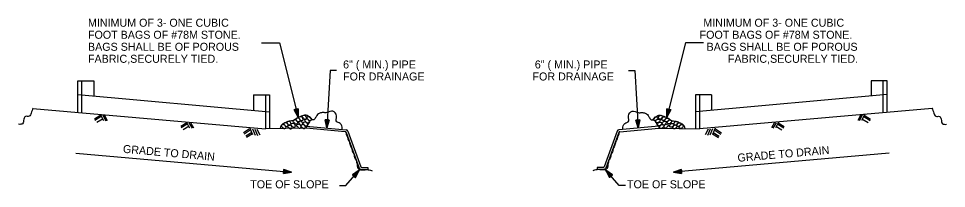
# Model space of a CAD drawing. Extents: x -41 to 251, y -169 to 237.
# Drawn here: x -40.56 to -7.34, y -129.36 to -123.29 of the extents above; entities that cross this region are included whole.
import ezdxf

# ---------------------------------------------------------------- set-up
doc = ezdxf.new("R2010")
doc.units = 0
for name, color, linetype in [('Arrowhead Terminators CELL', 7, 'Continuous'), ('Default', 7, 'Continuous'), ('Dimension Lines CELL', 7, 'Continuous'), ('Mis Object Lines', 7, 'Continuous'), ('Text CELL', 7, 'Continuous')]:
    doc.layers.add(name, color=color, linetype=linetype)

msp = doc.modelspace()

# ---------------------------------------------------------------- linework, layer by layer
at = {"layer": 'Arrowhead Terminators CELL'}
for points in [[(-30.624, -126.528), (-30.638, -126.531), (-30.554, -126.806), (-30.651, -126.535), (-30.665, -126.538), (-30.554, -126.806), (-30.679, -126.542), (-30.693, -126.545), (-30.554, -126.806), (-30.554, -126.51), (-30.568, -126.514), (-30.554, -126.806), (-30.582, -126.517), (-30.596, -126.521), (-30.554, -126.806), (-30.61, -126.524), (-30.693, -126.545), (-30.554, -126.51), (-30.554, -126.806), (-30.693, -126.545)], [(-17.277, -126.528), (-17.263, -126.531), (-17.347, -126.806), (-17.249, -126.535), (-17.236, -126.538), (-17.347, -126.806), (-17.222, -126.542), (-17.208, -126.545), (-17.347, -126.806), (-17.347, -126.51), (-17.333, -126.514), (-17.347, -126.806), (-17.319, -126.517), (-17.305, -126.521), (-17.347, -126.806), (-17.291, -126.524), (-17.208, -126.545), (-17.347, -126.51), (-17.347, -126.806), (-17.208, -126.545)], [(-29.507, -126.909), (-29.521, -126.908), (-29.524, -127.195), (-29.535, -126.907), (-29.549, -126.906), (-29.524, -127.195), (-29.564, -126.905), (-29.578, -126.905), (-29.524, -127.195), (-29.435, -126.913), (-29.449, -126.912), (-29.524, -127.195), (-29.464, -126.911), (-29.478, -126.911), (-29.524, -127.195), (-29.492, -126.91), (-29.578, -126.905), (-29.435, -126.913), (-29.524, -127.195), (-29.578, -126.905)], [(-18.394, -126.909), (-18.38, -126.908), (-18.377, -127.195), (-18.366, -126.907), (-18.352, -126.906), (-18.377, -127.195), (-18.337, -126.905), (-18.323, -126.905), (-18.377, -127.195), (-18.466, -126.913), (-18.452, -126.912), (-18.377, -127.195), (-18.437, -126.911), (-18.423, -126.911), (-18.377, -127.195), (-18.409, -126.91), (-18.323, -126.905), (-18.466, -126.913), (-18.377, -127.195), (-18.323, -126.905)], [(-31.073, -128.751), (-31.074, -128.765), (-30.787, -128.776), (-31.075, -128.78), (-31.076, -128.794), (-30.787, -128.776), (-31.077, -128.808), (-31.079, -128.823), (-30.787, -128.776), (-31.066, -128.68), (-31.068, -128.694), (-30.787, -128.776), (-31.069, -128.708), (-31.07, -128.723), (-30.787, -128.776), (-31.071, -128.737), (-31.079, -128.823), (-31.066, -128.68), (-30.787, -128.776), (-31.079, -128.823)], [(-28.553, -128.922), (-28.543, -128.932), (-28.364, -128.708), (-28.532, -128.941), (-28.521, -128.951), (-28.364, -128.708), (-28.511, -128.96), (-28.5, -128.97), (-28.364, -128.708), (-28.607, -128.875), (-28.596, -128.884), (-28.364, -128.708), (-28.586, -128.894), (-28.575, -128.903), (-28.364, -128.708), (-28.564, -128.913), (-28.5, -128.97), (-28.607, -128.875), (-28.364, -128.708), (-28.5, -128.97)], [(-19.348, -128.922), (-19.358, -128.932), (-19.537, -128.708), (-19.369, -128.941), (-19.38, -128.951), (-19.537, -128.708), (-19.39, -128.96), (-19.401, -128.97), (-19.537, -128.708), (-19.294, -128.875), (-19.305, -128.884), (-19.537, -128.708), (-19.315, -128.894), (-19.326, -128.903), (-19.537, -128.708), (-19.337, -128.913), (-19.401, -128.97), (-19.294, -128.875), (-19.537, -128.708), (-19.401, -128.97)], [(-16.828, -128.751), (-16.827, -128.765), (-17.114, -128.776), (-16.826, -128.78), (-16.825, -128.794), (-17.114, -128.776), (-16.824, -128.808), (-16.822, -128.823), (-17.114, -128.776), (-16.835, -128.68), (-16.833, -128.694), (-17.114, -128.776), (-16.832, -128.708), (-16.831, -128.723), (-17.114, -128.776), (-16.83, -128.737), (-16.822, -128.823), (-16.835, -128.68), (-17.114, -128.776), (-16.822, -128.823)]]:
    msp.add_lwpolyline(points, dxfattribs=at)
at = {"layer": 'Default'}
for p, q in [((-38.286, -126.661), (-38.286, -125.508)), ((-38.286, -125.508), (-37.857, -125.508)), ((-9.615, -125.508), (-10.044, -125.508)), ((-9.615, -126.661), (-9.615, -125.508)), ((-32.147, -126.014), (-31.717, -126.014)), ((-31.717, -126.014), (-31.717, -127.227)), ((-31.717, -126.014), (-31.574, -126.014)), ((-31.574, -126.014), (-31.574, -127.227)), ((-16.184, -126.014), (-16.327, -126.014)), ((-16.327, -126.014), (-16.327, -127.227)), ((-15.754, -126.014), (-16.184, -126.014)), ((-16.184, -126.014), (-16.184, -127.227)), ((-30.261, -127.137), (-30.267, -127.209)), ((-30.261, -127.137), (-28.834, -127.262)), ((-17.64, -127.137), (-19.067, -127.262)), ((-17.64, -127.137), (-17.634, -127.209)), ((-30.267, -127.209), (-31.723, -127.223)), ((-28.863, -127.332), (-30.267, -127.209)), ((-28.833, -127.355), (-28.368, -128.632)), ((-28.773, -127.309), (-28.309, -128.584)), ((-19.128, -127.309), (-19.592, -128.584)), ((-19.068, -127.355), (-19.533, -128.632)), ((-19.038, -127.332), (-17.634, -127.209)), ((-17.634, -127.209), (-16.178, -127.223)), ((-28.301, -128.679), (-28.055, -128.679)), ((-28.276, -128.608), (-28.055, -128.608)), ((-28.055, -128.608), (-28.055, -128.679)), ((-19.625, -128.608), (-19.846, -128.608)), ((-19.846, -128.608), (-19.846, -128.679)), ((-19.6, -128.679), (-19.846, -128.679))]:
    msp.add_line(p, q, dxfattribs=at)
for points in [[(-38.429, -126.645), (-38.429, -125.508), (-38.286, -125.508), (-38.286, -125.512)], [(-9.472, -126.645), (-9.472, -125.508), (-9.615, -125.508), (-9.615, -125.512)], [(-40.051, -126.495), (-31.723, -127.223)], [(-7.85, -126.495), (-16.178, -127.223)]]:
    msp.add_lwpolyline(points, dxfattribs=at)
for centre, radius, start, end in [((-28.866, -127.367), 0.0358, 20, 85), ((-28.841, -127.334), 0.0716, 20.0004, 85.0001), ((-19.06, -127.334), 0.0716, 94.9999, 159.9996), ((-19.035, -127.367), 0.0358, 95, 160), ((-28.301, -128.608), 0.0716, 200.0001, 270), ((-28.276, -128.572), 0.0358, 200.0006, 270), ((-19.625, -128.572), 0.0358, 270, 339.9994), ((-19.6, -128.608), 0.0716, 270, 339.9999)]:
    msp.add_arc(centre, radius, start, end, dxfattribs=at)
for points in [[(-40.037, -126.487), (-40.107, -126.666), (-40.177, -126.776), (-40.307, -126.786), (-40.367, -126.876), (-40.417, -127.046), (-40.557, -127.066)], [(-7.864, -126.487), (-7.794, -126.666), (-7.724, -126.776), (-7.594, -126.786), (-7.534, -126.876), (-7.484, -127.046), (-7.344, -127.066)], [(-30.05, -126.897), (-30.159, -126.794), (-30.305, -126.739), (-30.487, -126.8), (-30.597, -126.848), (-30.712, -126.927), (-30.87, -126.958), (-31.022, -127.012), (-31.156, -127.11), (-31.192, -127.207)], [(-30.469, -126.939), (-30.53, -126.848), (-30.585, -126.848), (-30.639, -126.885), (-30.621, -126.909), (-30.585, -126.952), (-30.542, -126.982), (-30.481, -126.964), (-30.469, -126.945)], [(-30.366, -126.891), (-30.427, -126.8), (-30.481, -126.8), (-30.536, -126.836), (-30.518, -126.86), (-30.481, -126.903), (-30.439, -126.933), (-30.378, -126.915), (-30.366, -126.897)], [(-30.244, -126.836), (-30.305, -126.745), (-30.36, -126.745), (-30.415, -126.781), (-30.396, -126.806), (-30.36, -126.848), (-30.317, -126.879), (-30.256, -126.86), (-30.244, -126.842)], [(-28.968, -127.231), (-29.047, -127.031), (-29.169, -126.976), (-29.181, -126.769), (-29.302, -126.593), (-29.527, -126.648), (-29.655, -126.648), (-29.776, -126.666), (-29.91, -126.794), (-29.983, -126.903), (-30.086, -126.915), (-30.165, -127.012), (-30.25, -127.134)], [(-30.074, -126.891), (-30.135, -126.8), (-30.19, -126.8), (-30.244, -126.836), (-30.226, -126.86), (-30.19, -126.903), (-30.147, -126.933), (-30.086, -126.915), (-30.074, -126.897)], [(-18.933, -127.231), (-18.854, -127.031), (-18.732, -126.976), (-18.72, -126.769), (-18.599, -126.593), (-18.374, -126.648), (-18.246, -126.648), (-18.125, -126.666), (-17.991, -126.794), (-17.918, -126.903), (-17.815, -126.915), (-17.736, -127.012), (-17.651, -127.134)], [(-17.851, -126.897), (-17.742, -126.794), (-17.596, -126.739), (-17.414, -126.8), (-17.304, -126.848), (-17.189, -126.927), (-17.031, -126.958), (-16.879, -127.012), (-16.745, -127.11), (-16.709, -127.207)], [(-17.827, -126.891), (-17.766, -126.8), (-17.711, -126.8), (-17.657, -126.836), (-17.675, -126.86), (-17.711, -126.903), (-17.754, -126.933), (-17.815, -126.915), (-17.827, -126.897)], [(-17.657, -126.836), (-17.596, -126.745), (-17.541, -126.745), (-17.486, -126.781), (-17.505, -126.806), (-17.541, -126.848), (-17.584, -126.879), (-17.644, -126.86), (-17.657, -126.842)], [(-17.535, -126.891), (-17.474, -126.8), (-17.42, -126.8), (-17.365, -126.836), (-17.383, -126.86), (-17.42, -126.903), (-17.462, -126.933), (-17.523, -126.915), (-17.535, -126.897)], [(-17.432, -126.939), (-17.371, -126.848), (-17.316, -126.848), (-17.262, -126.885), (-17.28, -126.909), (-17.316, -126.952), (-17.359, -126.982), (-17.42, -126.964), (-17.432, -126.945)], [(-30.986, -127.17), (-31.046, -127.079), (-31.101, -127.079), (-31.156, -127.116), (-31.138, -127.14), (-31.101, -127.183), (-31.059, -127.213), (-30.998, -127.195), (-30.986, -127.176)], [(-30.895, -127.104), (-30.955, -127.012), (-31.01, -127.012), (-31.065, -127.049), (-31.046, -127.073), (-31.01, -127.116), (-30.968, -127.146), (-30.907, -127.128), (-30.895, -127.11)], [(-30.797, -127.055), (-30.858, -126.964), (-30.913, -126.964), (-30.968, -127), (-30.949, -127.025), (-30.913, -127.067), (-30.87, -127.097), (-30.81, -127.079), (-30.797, -127.061)], [(-30.761, -127.183), (-30.822, -127.091), (-30.876, -127.091), (-30.931, -127.128), (-30.913, -127.152), (-30.876, -127.195), (-30.834, -127.225), (-30.773, -127.207), (-30.761, -127.189)], [(-30.645, -127.128), (-30.706, -127.037), (-30.761, -127.037), (-30.816, -127.073), (-30.797, -127.097), (-30.761, -127.14), (-30.718, -127.17), (-30.658, -127.152), (-30.645, -127.134)], [(-30.566, -127.006), (-30.627, -126.915), (-30.682, -126.915), (-30.737, -126.952), (-30.718, -126.976), (-30.682, -127.018), (-30.639, -127.049), (-30.579, -127.031), (-30.566, -127.012)], [(-30.439, -127.158), (-30.5, -127.067), (-30.554, -127.067), (-30.609, -127.104), (-30.591, -127.128), (-30.554, -127.17), (-30.512, -127.201), (-30.451, -127.183), (-30.439, -127.164)], [(-30.378, -127.049), (-30.439, -126.958), (-30.493, -126.958), (-30.548, -126.994), (-30.53, -127.018), (-30.493, -127.061), (-30.451, -127.091), (-30.39, -127.073), (-30.378, -127.055)], [(-30.287, -127.17), (-30.348, -127.079), (-30.402, -127.079), (-30.457, -127.116), (-30.439, -127.14), (-30.402, -127.183), (-30.36, -127.213), (-30.299, -127.195), (-30.287, -127.176)], [(-30.208, -127.079), (-30.269, -126.988), (-30.323, -126.988), (-30.378, -127.025), (-30.36, -127.049), (-30.323, -127.091), (-30.281, -127.122), (-30.22, -127.104), (-30.208, -127.085)], [(-30.147, -126.976), (-30.208, -126.885), (-30.263, -126.885), (-30.317, -126.921), (-30.299, -126.945), (-30.263, -126.988), (-30.22, -127.018), (-30.159, -127), (-30.147, -126.982)], [(-17.754, -126.976), (-17.693, -126.885), (-17.638, -126.885), (-17.584, -126.921), (-17.602, -126.945), (-17.638, -126.988), (-17.681, -127.018), (-17.742, -127), (-17.754, -126.982)], [(-17.693, -127.079), (-17.632, -126.988), (-17.578, -126.988), (-17.523, -127.025), (-17.541, -127.049), (-17.578, -127.091), (-17.62, -127.122), (-17.681, -127.104), (-17.693, -127.085)], [(-17.614, -127.17), (-17.553, -127.079), (-17.499, -127.079), (-17.444, -127.116), (-17.462, -127.14), (-17.499, -127.183), (-17.541, -127.213), (-17.602, -127.195), (-17.614, -127.176)], [(-17.523, -127.049), (-17.462, -126.958), (-17.408, -126.958), (-17.353, -126.994), (-17.371, -127.018), (-17.408, -127.061), (-17.45, -127.091), (-17.511, -127.073), (-17.523, -127.055)], [(-17.462, -127.158), (-17.401, -127.067), (-17.347, -127.067), (-17.292, -127.104), (-17.31, -127.128), (-17.347, -127.17), (-17.389, -127.201), (-17.45, -127.183), (-17.462, -127.164)], [(-17.335, -127.006), (-17.274, -126.915), (-17.219, -126.915), (-17.164, -126.952), (-17.183, -126.976), (-17.219, -127.018), (-17.262, -127.049), (-17.322, -127.031), (-17.335, -127.012)], [(-17.256, -127.128), (-17.195, -127.037), (-17.14, -127.037), (-17.085, -127.073), (-17.104, -127.097), (-17.14, -127.14), (-17.183, -127.17), (-17.243, -127.152), (-17.256, -127.134)], [(-17.14, -127.183), (-17.079, -127.091), (-17.025, -127.091), (-16.97, -127.128), (-16.988, -127.152), (-17.025, -127.195), (-17.067, -127.225), (-17.128, -127.207), (-17.14, -127.189)], [(-17.104, -127.055), (-17.043, -126.964), (-16.988, -126.964), (-16.933, -127), (-16.952, -127.025), (-16.988, -127.067), (-17.031, -127.097), (-17.091, -127.079), (-17.104, -127.061)], [(-17.006, -127.104), (-16.946, -127.012), (-16.891, -127.012), (-16.836, -127.049), (-16.854, -127.073), (-16.891, -127.116), (-16.933, -127.146), (-16.994, -127.128), (-17.006, -127.11)], [(-16.915, -127.17), (-16.854, -127.079), (-16.8, -127.079), (-16.745, -127.116), (-16.763, -127.14), (-16.8, -127.183), (-16.842, -127.213), (-16.903, -127.195), (-16.915, -127.176)], [(-28.846, -127.347), (-28.825, -127.42), (-28.798, -127.496), (-28.777, -127.538), (-28.761, -127.62), (-28.731, -127.66), (-28.691, -127.799), (-28.628, -127.939), (-28.585, -128.082), (-28.549, -128.143), (-28.543, -128.2), (-28.479, -128.34), (-28.442, -128.498), (-28.369, -128.678), (-28.257, -128.687), (-28.187, -128.69), (-28.108, -128.684), (-28.041, -128.687), (-27.962, -128.705), (-27.895, -128.729)], [(-19.055, -127.347), (-19.076, -127.42), (-19.103, -127.496), (-19.124, -127.538), (-19.14, -127.62), (-19.17, -127.66), (-19.21, -127.799), (-19.273, -127.939), (-19.316, -128.082), (-19.352, -128.143), (-19.358, -128.2), (-19.422, -128.34), (-19.459, -128.498), (-19.532, -128.678), (-19.644, -128.687), (-19.714, -128.69), (-19.793, -128.684), (-19.86, -128.687), (-19.939, -128.705), (-20.006, -128.729)]]:
    msp.add_spline(points, degree=3, dxfattribs=at)
at = {"layer": 'Dimension Lines CELL'}
for p, q in [((-31.861, -124.151), (-31.218, -124.151)), ((-31.218, -124.151), (-30.554, -126.806)), ((-16.683, -124.151), (-17.347, -126.806)), ((-16.04, -124.151), (-16.683, -124.151)), ((-29.4, -125.143), (-29.524, -127.195)), ((-29.171, -125.143), (-29.4, -125.143)), ((-18.73, -125.143), (-18.501, -125.143)), ((-18.501, -125.143), (-18.377, -127.195)), ((-37.616, -126.743), (-37.835, -126.876)), ((-37.604, -126.791), (-37.823, -126.925)), ((-37.531, -126.864), (-37.75, -126.998)), ((-37.628, -126.73), (-37.519, -126.925)), ((-37.543, -126.743), (-37.434, -126.937)), ((-37.494, -126.73), (-37.385, -126.925)), ((-10.407, -126.73), (-10.516, -126.925)), ((-10.358, -126.743), (-10.467, -126.937)), ((-10.273, -126.73), (-10.382, -126.925)), ((-10.37, -126.864), (-10.151, -126.998)), ((-10.297, -126.791), (-10.078, -126.925)), ((-10.285, -126.743), (-10.066, -126.876)), ((-34.529, -127.012), (-34.748, -127.146)), ((-34.517, -127.061), (-34.736, -127.195)), ((-34.444, -127.134), (-34.663, -127.268)), ((-34.541, -127), (-34.432, -127.195)), ((-34.456, -127.012), (-34.347, -127.207)), ((-34.407, -127), (-34.298, -127.195)), ((-13.493, -127), (-13.603, -127.195)), ((-13.445, -127.012), (-13.554, -127.207)), ((-13.36, -127), (-13.469, -127.195)), ((-13.457, -127.134), (-13.238, -127.268)), ((-13.384, -127.061), (-13.165, -127.195)), ((-13.372, -127.012), (-13.153, -127.146)), ((-32.293, -127.231), (-32.511, -127.365)), ((-32.268, -127.28), (-32.487, -127.413)), ((-32.207, -127.353), (-32.426, -127.486)), ((-32.183, -127.401), (-32.402, -127.535)), ((-32.28, -127.207), (-32.183, -127.426)), ((-32.183, -127.231), (-32.086, -127.45)), ((-32.098, -127.243), (-32.001, -127.462)), ((-32.025, -127.243), (-31.916, -127.438)), ((-15.876, -127.243), (-15.985, -127.438)), ((-15.803, -127.243), (-15.9, -127.462)), ((-15.718, -127.231), (-15.815, -127.45)), ((-15.621, -127.207), (-15.718, -127.426)), ((-15.718, -127.401), (-15.499, -127.535)), ((-15.694, -127.353), (-15.475, -127.486)), ((-15.633, -127.28), (-15.414, -127.413)), ((-15.608, -127.231), (-15.39, -127.365)), ((-38.507, -128.101), (-30.787, -128.776)), ((-9.394, -128.101), (-17.114, -128.776)), ((-28.841, -129.246), (-28.364, -128.708)), ((-19.06, -129.246), (-19.537, -128.708)), ((-29.07, -129.246), (-28.841, -129.246)), ((-18.831, -129.246), (-19.06, -129.246))]:
    msp.add_line(p, q, dxfattribs=at)
at = {"layer": 'Mis Object Lines'}
for p, q in [((-37.857, -125.508), (-37.857, -126.054)), ((-10.044, -125.508), (-10.044, -126.054)), ((-38.429, -126.002), (-31.574, -126.624)), ((-32.147, -126.014), (-32.147, -126.572)), ((-9.472, -126.002), (-16.327, -126.624)), ((-15.754, -126.014), (-15.754, -126.572))]:
    msp.add_line(p, q, dxfattribs=at)

# ---------------------------------------------------------------- texts
at = {"layer": 'Text CELL'}
for s, height, p in [('MINIMUM OF 3- ONE CUBIC', 0.28639, (-38.072, -123.58)), ('MINIMUM OF 3- ONE CUBIC', 0.28639, (-16.047, -123.58)), ('FOOT BAGS OF #78M STONE.', 0.28638, (-38.072, -124.009)), ('FOOT BAGS OF #78M STONE.', 0.28638, (-16.18, -124.009)), ('BAGS SHALL BE OF POROUS', 0.28638, (-38.072, -124.439)), ('BAGS SHALL BE OF POROUS', 0.28638, (-15.93, -124.439)), ('FABRIC,SECURELY TIED.', 0.28639, (-38.072, -124.868)), ('6" ( MIN.) PIPE', 0.28638, (-28.94, -125.07)), ('6" ( MIN.) PIPE', 0.28638, (-22.078, -125.07)), ('FABRIC,SECURELY TIED.', 0.28639, (-15.168, -124.868)), ('FOR DRAINAGE', 0.28638, (-28.94, -125.5)), ('FOR DRAINAGE', 0.28638, (-22.161, -125.5)), ('TOE OF SLOPE', 0.28638, (-32.264, -129.351)), ('TOE OF SLOPE', 0.28638, (-18.778, -129.351))]:
    msp.add_text(s, height=height, dxfattribs=at).set_placement(p)
for rotation, p in [(355.0003, (-36.829, -128.08)), (4.9997, (-14.81, -128.407))]:
    msp.add_text('GRADE TO DRAIN', height=0.28639, rotation=rotation, dxfattribs=at).set_placement(p)

doc.saveas('drawing.dxf')
